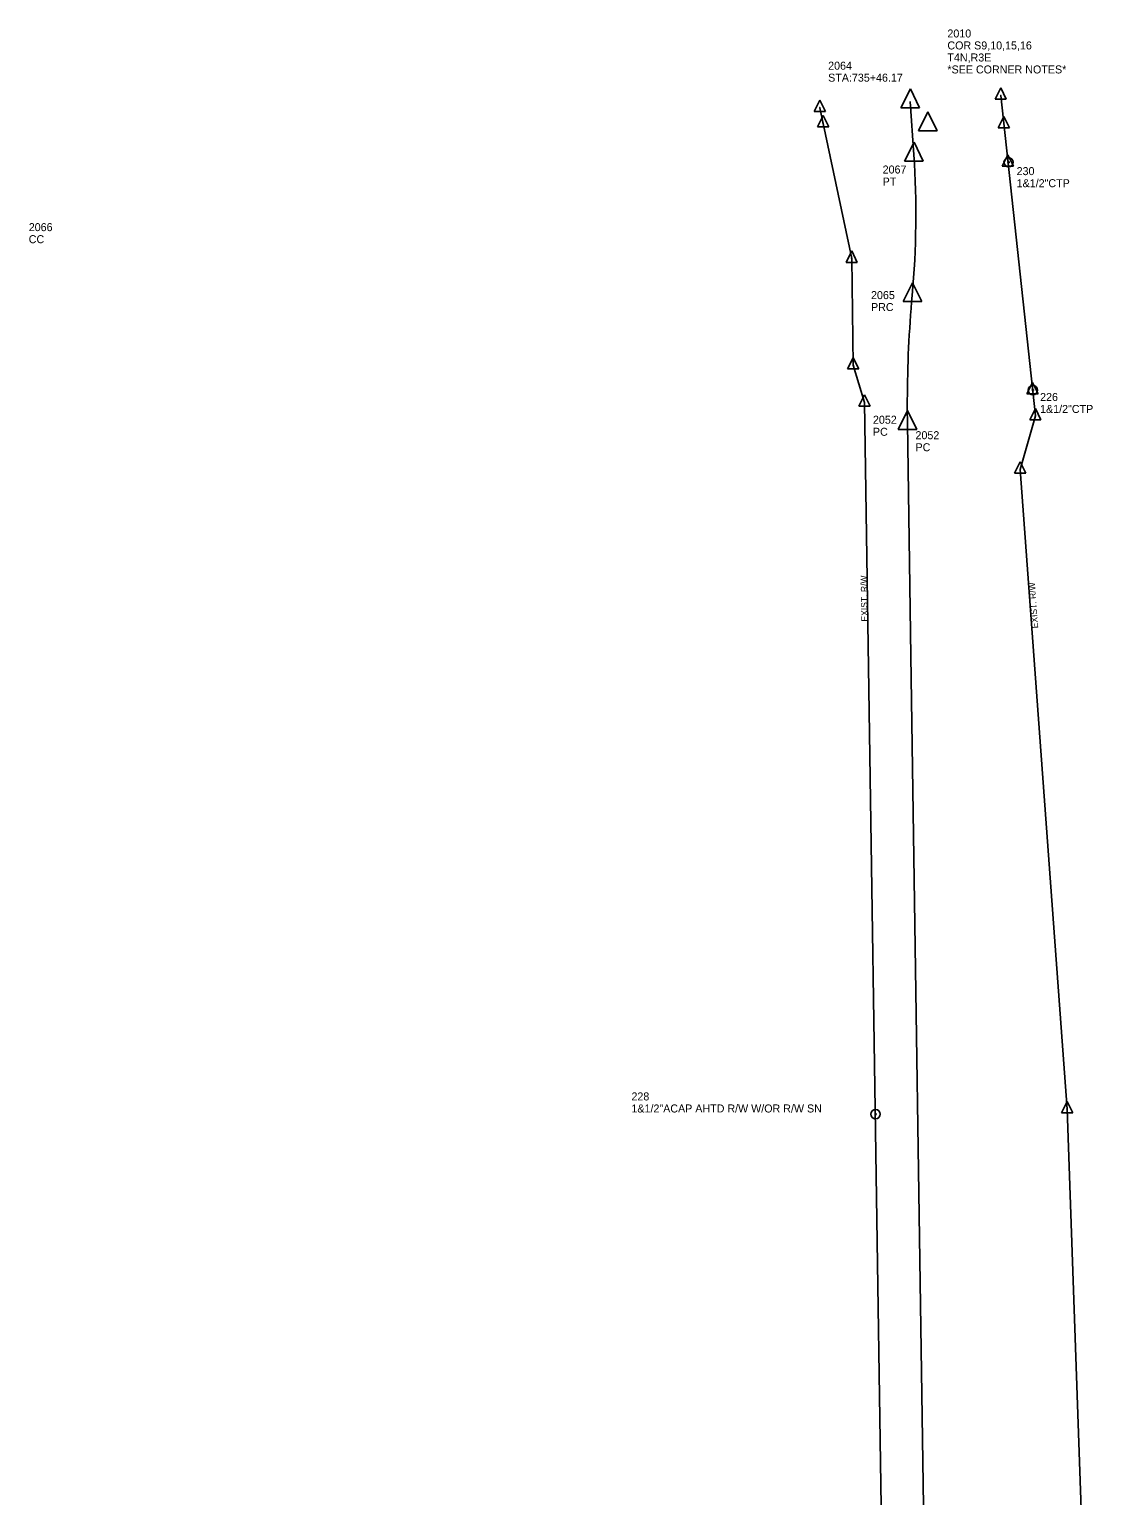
# Model space of a CAD drawing. Extents: x 1674300 to 1677561, y 225056 to 231852.
# Drawn here: x 1676517 to 1677514, y 230473 to 231847 of the extents above; entities that cross this region are included whole.
import ezdxf

# ---------------------------------------------------------------- set-up
doc = ezdxf.new("R2010")
doc.units = 0
for name, color, linetype in [('R_Annotation', 7, 'Continuous'), ('S_CAL_CORNER', 7, 'Continuous'), ('S_CAL_CORNER_ANNOT', 7, 'Continuous'), ('S_EXIST_ROW', 7, 'Continuous'), ('S_EXISTING_ALIGNMENT', 7, 'Continuous'), ('S_IRON_PIN', 7, 'Continuous'), ('S_IRON_PIN_ANNOT', 7, 'Continuous')]:
    doc.layers.add(name, color=color, linetype=linetype)

msp = doc.modelspace()

# ---------------------------------------------------------------- linework, layer by layer
at = {"layer": 'S_CAL_CORNER'}
for p, q in [((1677342.9, 231791.4), (1677334.1, 231773.6)), ((1677342.9, 231791.4), (1677334.1, 231773.6)), ((1677342.9, 231791.4), (1677351.6, 231773.6)), ((1677342.9, 231791.4), (1677351.6, 231773.6)), ((1677334.1, 231773.6), (1677351.6, 231773.6)), ((1677334.1, 231773.6), (1677351.6, 231773.6)), ((1677359.3, 231769.7), (1677350.5, 231752)), ((1677359.3, 231769.7), (1677368, 231752)), ((1677350.5, 231752), (1677368, 231752)), ((1677346.3, 231741.4), (1677337.5, 231723.6)), ((1677346.3, 231741.4), (1677355, 231723.6)), ((1677337.5, 231723.6), (1677355, 231723.6)), ((1677344.8, 231609.7), (1677336, 231592)), ((1677344.8, 231609.7), (1677353.5, 231592)), ((1677336, 231592), (1677353.5, 231592)), ((1677340.3, 231490), (1677331.5, 231472.2)), ((1677340.3, 231490), (1677331.5, 231472.2)), ((1677340.3, 231490), (1677349, 231472.2)), ((1677340.3, 231490), (1677349, 231472.2)), ((1677331.5, 231472.2), (1677349, 231472.2)), ((1677331.5, 231472.2), (1677349, 231472.2))]:
    msp.add_line(p, q, dxfattribs=at)
at = {"layer": 'S_EXIST_ROW'}
for p, q in [((1677427.6, 231792.2), (1677422.3, 231781.6)), ((1677427.6, 231792.2), (1677432.8, 231781.6)), ((1677427.6, 231785.1), (1677427.6, 231785.1)), ((1677460.1, 231484.8), (1677427.6, 231785.1)), ((1677258, 231780.8), (1677252.7, 231770.1)), ((1677258, 231780.8), (1677263.2, 231770.1)), ((1677258, 231773.7), (1677258, 231773.7)), ((1677287.9, 231632.3), (1677258, 231773.7)), ((1677422.3, 231781.6), (1677432.8, 231781.6)), ((1677252.7, 231770.1), (1677263.2, 231770.1)), ((1677261, 231766.3), (1677255.7, 231755.7)), ((1677261, 231766.3), (1677266.3, 231755.7)), ((1677261, 231759.2), (1677261, 231759.2)), ((1677430.5, 231765.5), (1677425.2, 231754.9)), ((1677430.5, 231765.5), (1677435.7, 231754.9)), ((1677430.5, 231758.5), (1677430.5, 231758.5)), ((1677255.7, 231755.7), (1677266.3, 231755.7)), ((1677425.2, 231754.9), (1677435.7, 231754.9)), ((1677434.4, 231729.6), (1677429.1, 231718.9)), ((1677429.1, 231718.9), (1677439.6, 231718.9)), ((1677434.4, 231729.6), (1677439.6, 231718.9)), ((1677434.4, 231722.5), (1677434.4, 231722.5)), ((1677287.9, 231639.4), (1677282.6, 231628.7)), ((1677287.9, 231639.4), (1677293.1, 231628.7)), ((1677282.6, 231628.7), (1677293.1, 231628.7)), ((1677287.9, 231632.3), (1677287.9, 231632.3)), ((1677289.4, 231532.3), (1677287.9, 231632.3)), ((1677289.4, 231539.4), (1677284.1, 231528.8)), ((1677289.4, 231539.4), (1677294.6, 231528.8)), ((1677284.1, 231528.8), (1677294.6, 231528.8)), ((1677289.4, 231532.3), (1677289.4, 231532.3)), ((1677299.9, 231497.5), (1677289.4, 231532.3)), ((1677457.5, 231516.1), (1677452.2, 231505.5)), ((1677457.5, 231516.1), (1677462.7, 231505.5)), ((1677299.9, 231504.6), (1677294.6, 231493.9)), ((1677299.9, 231504.6), (1677305.1, 231493.9)), ((1677299.9, 231497.5), (1677299.9, 231497.5)), ((1677337.1, 229010.5), (1677299.9, 231497.5)), ((1677452.2, 231505.5), (1677462.7, 231505.5)), ((1677457.5, 231509), (1677457.5, 231509)), ((1677294.6, 231493.9), (1677305.1, 231493.9)), ((1677445.8, 231434.6), (1677460.1, 231484.8)), ((1677460.1, 231491.9), (1677454.8, 231481.3)), ((1677460.1, 231491.9), (1677465.3, 231481.3)), ((1677460.1, 231484.8), (1677460.1, 231484.8)), ((1677454.8, 231481.3), (1677465.3, 231481.3)), ((1677445.9, 231441.7), (1677440.6, 231431.1)), ((1677445.9, 231441.7), (1677451.1, 231431.1)), ((1677440.6, 231431.1), (1677451.1, 231431.1)), ((1677445.8, 231434.6), (1677445.8, 231434.6)), ((1677489.8, 230835.2), (1677445.8, 231434.6)), ((1677489.8, 230842.3), (1677484.5, 230831.7)), ((1677489.8, 230842.3), (1677495.1, 230831.7)), ((1677484.5, 230831.7), (1677495.1, 230831.7)), ((1677489.8, 230835.2), (1677489.8, 230835.2)), ((1677507.3, 230335.4), (1677489.8, 230835.2))]:
    msp.add_line(p, q, dxfattribs=at)
for centre, radius in [((1677427.6, 231785.1), 0.18), ((1677427.6, 231785.1), 0.09), ((1677258, 231773.7), 0.18), ((1677258, 231773.7), 0.09), ((1677261, 231759.2), 0.18), ((1677261, 231759.2), 0.09), ((1677430.5, 231758.5), 0.18), ((1677430.5, 231758.5), 0.09), ((1677434.4, 231722.5), 0.18), ((1677434.4, 231722.5), 0.09), ((1677287.9, 231632.3), 0.18), ((1677287.9, 231632.3), 0.09), ((1677289.4, 231532.3), 0.18), ((1677289.4, 231532.3), 0.09), ((1677299.9, 231497.5), 0.18), ((1677299.9, 231497.5), 0.09), ((1677457.5, 231509), 0.18), ((1677457.5, 231509), 0.09), ((1677460.1, 231484.8), 0.18), ((1677460.1, 231484.8), 0.09), ((1677445.8, 231434.6), 0.18), ((1677445.8, 231434.6), 0.09), ((1677489.8, 230835.2), 0.18), ((1677489.8, 230835.2), 0.09)]:
    msp.add_circle(centre, radius, dxfattribs=at)
at = {"layer": 'S_EXISTING_ALIGNMENT'}
for p, q in [((1677346.1, 231729.4), (1677342.8, 231779.4)), ((1677343.4, 231260), (1677340.2, 231478)), ((1677375.2, 229134.4), (1677343.4, 231260))]:
    msp.add_line(p, q, dxfattribs=at)
for centre, radius, start, end in [((1676508.9, 231673), 839.1, 354.8568, 3.8568), ((1678484.9, 231495.1), 1144.9, 174.8568, 179.7923), ((1678484.9, 231495.1), 1144.9, 179.7923, 180.8568)]:
    msp.add_arc(centre, radius, start, end, dxfattribs=at)
at = {"layer": 'S_IRON_PIN'}
for centre, radius in [((1677435, 231722.5), 4.36), ((1677435, 231722.5), 0.617), ((1677435, 231722.5), 0.392), ((1677435, 231722.5), 0.317), ((1677435, 231722.5), 0.218), ((1677435, 231722.5), 0.0872), ((1677435, 231722.5), 0.123), ((1677457.8, 231509), 4.36), ((1677457.8, 231509), 0.617), ((1677457.8, 231509), 0.392), ((1677457.8, 231509), 0.317), ((1677457.8, 231509), 0.218), ((1677457.8, 231509), 0.0872), ((1677457.8, 231509), 0.123), ((1677310.3, 230830.4), 4.36), ((1677310.3, 230830.4), 0.617), ((1677310.3, 230830.4), 0.392), ((1677310.3, 230830.4), 0.317), ((1677310.3, 230830.4), 0.218), ((1677310.3, 230830.4), 0.0872), ((1677310.3, 230830.4), 0.123)]:
    msp.add_circle(centre, radius, dxfattribs=at)

# ---------------------------------------------------------------- texts
at = {"layer": 'R_Annotation'}
for rotation, p in [(90.8568, (1677302.9, 231292.1)), (94.1953, (1677462.8, 231285.9))]:
    msp.add_text('EXIST. R/W', height=6, rotation=rotation, dxfattribs=at).set_placement(p)
at = {"layer": 'S_CAL_CORNER_ANNOT'}
for s, p in [('2010', (1677377.6, 231839.5)), ('COR S9,10,15,16', (1677377.6, 231828.3)), ('2064', (1677265.8, 231809.3)), ('*SEE CORNER NOTES*', (1677377.6, 231805.8)), ('T4N,R3E', (1677377.6, 231817)), ('STA:735+46.17', (1677265.8, 231798.1)), ('2067', (1677316.9, 231712)), ('PT', (1677316.9, 231700.7)), ('2066', (1676516.4, 231658)), ('CC', (1676516.4, 231646.7)), ('2065', (1677306, 231594.3)), ('PRC', (1677306, 231583.1)), ('2052', (1677307.8, 231477.5)), ('PC', (1677307.8, 231466.2)), ('2052', (1677347.7, 231463)), ('PC', (1677347.7, 231451.7))]:
    msp.add_text(s, height=7.5, dxfattribs=at).set_placement(p)
at = {"layer": 'S_IRON_PIN_ANNOT'}
for s, p in [('230', (1677442.5, 231710.5)), ('1&1/2"CTP ', (1677442.5, 231699.2)), ('226', (1677464.5, 231498.8)), ('1&1/2"CTP ', (1677464.5, 231487.6)), ('228', (1677081.4, 230843.3)), ('1&1/2"ACAP AHTD R/W W/OR R/W SN', (1677081.4, 230832))]:
    msp.add_text(s, height=7.5, dxfattribs=at).set_placement(p)

doc.saveas('drawing.dxf')
